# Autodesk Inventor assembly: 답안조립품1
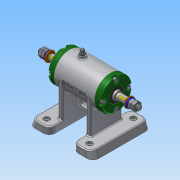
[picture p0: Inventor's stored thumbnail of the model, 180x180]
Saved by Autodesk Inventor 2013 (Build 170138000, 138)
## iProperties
Created: 2016-07
Part Number: 답안조립품1
Document SubType Name: Assembly
Designer: Administrator
Author: Administrator
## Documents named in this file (14)
- C:\Users\Administrator\Desktop\460708V1003\답안조립품1.iam
- C:\Users\Administrator\Desktop\460708V1003\본체.ipt
- C:\Users\Administrator\Desktop\460708V1003\스퍼기어.ipt
- C:\Users\Administrator\Desktop\460708V1003\축.ipt
- C:\Users\Administrator\Desktop\460708V1003\키 3 x 3 x 12.ipt
- C:\Users\Administrator\Desktop\460708V1003\V벨트풀리.ipt
- C:\Users\Administrator\Desktop\460708V1003\너트 M 8.ipt
- C:\Users\Administrator\Desktop\460708V1003\스프링와셔 8.ipt
- C:\Users\Administrator\Desktop\460708V1003\와셔 8x17.ipt
- C:\Users\Administrator\Desktop\460708V1003\오일 실 15 25 7.ipt
- C:\Users\Administrator\Desktop\460708V1003\커버.ipt
- C:\Users\Administrator\Desktop\460708V1003\베어링 15 x 32 x 9.ipt
- C:\Users\Administrator\Desktop\460708V1003\니플 M 6 x 0.75.ipt
- C:\Users\Administrator\Desktop\460708V1003\볼트 M4 x 12.ipt
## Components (11 placed, 3 different names)
1. V벨트풀리:1
2. KS B 2023 6002 - 15 x 32 x 9:1
3. KS B 2023 6002 - 15 x 32 x 9:2
4. ISO 4762 M4 x 12:2
5. ISO 4762 M4 x 12:3
6. ISO 4762 M4 x 12:4
7. ISO 4762 M4 x 12:5
8. ISO 4762 M4 x 12:1
9. ISO 4762 M4 x 12:6
10. ISO 4762 M4 x 12:7
11. ISO 4762 M4 x 12:8
